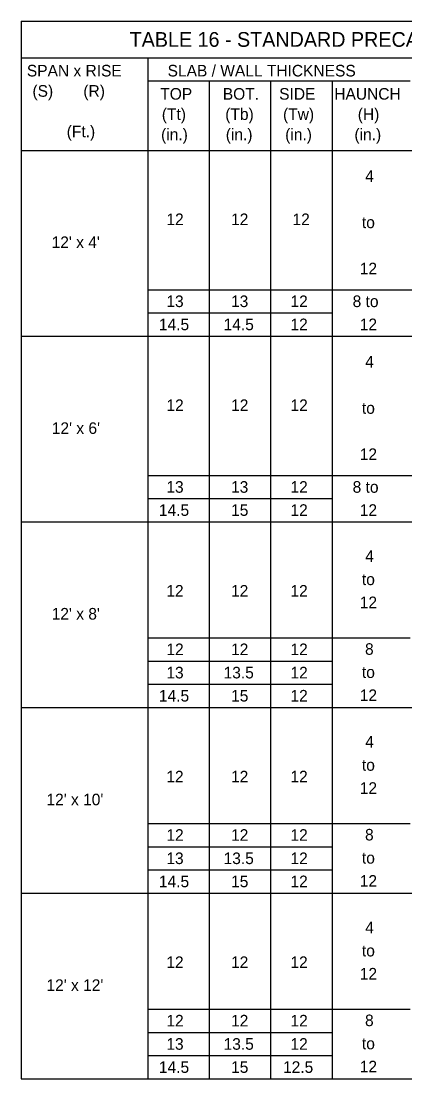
# Model space of a CAD drawing. Extents: x 10340.6 to 10376, y 76398.7 to 76415.8.
# Drawn here: x 10341.03 to 10344.36, y 76405.12 to 76414.31 of the extents above; entities that cross this region are included whole.
import ezdxf

# ---------------------------------------------------------------- set-up
doc = ezdxf.new("R2010")
doc.units = 0
doc.layers.add('AdhocPoint_dp', color=7, linetype='Continuous')
doc.layers.add('PlotBorder_dp', color=7, linetype='Continuous')

msp = doc.modelspace()

# ---------------------------------------------------------------- linework, layer by layer
at = {"layer": 'PlotBorder_dp'}
for p, q in [((10341.0317, 76414.3084), (10341.0317, 76405.1209)), ((10341.0317, 76414.3084), (10350.5475, 76414.3084)), ((10341.0317, 76413.9906), (10350.5475, 76413.9906)), ((10342.1299, 76413.9906), (10342.1299, 76405.1209)), ((10342.1299, 76413.789), (10344.409, 76413.789)), ((10342.6637, 76413.789), (10342.6637, 76405.1209)), ((10343.1974, 76413.789), (10343.1974, 76405.1209)), ((10343.7312, 76413.789), (10343.7312, 76405.1209)), ((10341.0317, 76413.185), (10350.5475, 76413.185)), ((10342.1299, 76411.9753), (10349.3093, 76411.9753)), ((10342.1299, 76411.7737), (10343.7312, 76411.7737)), ((10341.0317, 76411.5721), (10349.3093, 76411.5721)), ((10342.1299, 76410.3625), (10349.3093, 76410.3625)), ((10342.1299, 76410.1609), (10343.7312, 76410.1609)), ((10342.1299, 76410.1606), (10343.7312, 76410.1606)), ((10341.0317, 76409.9593), (10349.3093, 76409.9593)), ((10342.1299, 76408.9513), (10344.409, 76408.9513)), ((10342.1299, 76408.7497), (10343.7312, 76408.7497)), ((10342.1299, 76408.5481), (10343.7312, 76408.5481)), ((10341.0317, 76408.3465), (10349.3093, 76408.3465)), ((10342.1299, 76407.3385), (10344.409, 76407.3385)), ((10342.1299, 76407.1369), (10343.7312, 76407.1369)), ((10342.1299, 76406.9353), (10343.7312, 76406.9353)), ((10341.0317, 76406.7337), (10349.3093, 76406.7337)), ((10342.1299, 76405.7257), (10344.409, 76405.7257)), ((10342.1299, 76405.5241), (10343.7312, 76405.5241)), ((10342.1299, 76405.3225), (10343.7312, 76405.3225)), ((10341.0317, 76405.1209), (10350.5475, 76405.1209))]:
    msp.add_line(p, q, dxfattribs=at)

# ---------------------------------------------------------------- texts
at = {"layer": 'AdhocPoint_dp'}
for s, height, p in [('TABLE 16 - STANDARD PRECAST BOX CULVERT DESIGNS (3" COVER) - 12\' SPANS', 0.128, (10341.9731, 76414.0855)), ('SLAB / WALL THICKNESS', 0.1008, (10342.303, 76413.828)), ('12', 0.1008, (10342.2922, 76412.5368)), ('12', 0.1008, (10342.8536, 76412.5368)), ('12', 0.1008, (10343.3874, 76412.5368)), ("12' x 4'", 0.1008, (10341.2963, 76412.3377))]:
    msp.add_text(s, height=height, dxfattribs=at).set_placement(p)
at = {"layer": 'PlotBorder_dp'}
for s, p in [('SPAN x RISE', (10341.0811, 76413.828)), ('(S)       (R)', (10341.1298, 76413.652)), ('TOP', (10342.2391, 76413.6264)), ('BOT.', (10342.782, 76413.6264)), ('SIDE', (10343.2715, 76413.6264)), ('HAUNCH', (10343.7498, 76413.6264)), ('(Tt)', (10342.2526, 76413.4504)), ('(Tb)', (10342.8034, 76413.4504)), ('(Tw)', (10343.3051, 76413.4504)), ('(H)', (10343.9536, 76413.4504)), ('(Ft.)', (10341.427, 76413.3)), ('(in.)', (10342.2463, 76413.2744)), ('(in.)', (10342.8078, 76413.2744)), ('(in.)', (10343.3236, 76413.2744)), ('(in.)', (10343.9247, 76413.2744)), ('4', (10344.0183, 76412.9123)), ('to', (10343.9898, 76412.5107)), ('12', (10343.971, 76412.1091)), ('13', (10342.2921, 76411.8247)), ('13', (10342.8536, 76411.8247)), ('12', (10343.3695, 76411.8247)), ('8 to', (10343.9092, 76411.8247)), ('14.5', (10342.2275, 76411.6239)), ('14.5', (10342.789, 76411.6239)), ('12', (10343.3695, 76411.6239)), ('12', (10343.971, 76411.6239)), ('4', (10344.0183, 76411.2995)), ('12', (10342.2927, 76410.9219)), ('12', (10342.8541, 76410.9219)), ('12', (10343.3699, 76410.9219)), ('to', (10343.9898, 76410.8979)), ("12' x 6'", (10341.2974, 76410.7228)), ('12', (10343.971, 76410.4963)), ('13', (10342.2921, 76410.2119)), ('13', (10342.8536, 76410.2119)), ('12', (10343.3695, 76410.2119)), ('8 to', (10343.9092, 76410.2119)), ('14.5', (10342.2275, 76410.0111)), ('15', (10342.8541, 76410.0111)), ('12', (10343.3695, 76410.0111)), ('12', (10343.971, 76410.0111)), ('4', (10344.0183, 76409.6108)), ('to', (10343.9898, 76409.41)), ('12', (10342.2918, 76409.3094)), ('12', (10342.8533, 76409.3094)), ('12', (10343.3691, 76409.3094)), ('12', (10343.971, 76409.2092)), ("12' x 8'", (10341.2966, 76409.1103)), ('12', (10342.2922, 76408.8015)), ('12', (10342.8536, 76408.8015)), ('12', (10343.3694, 76408.8015)), ('8', (10344.0166, 76408.8041)), ('13', (10342.2921, 76408.5991)), ('13.5', (10342.789, 76408.5991)), ('12', (10343.3695, 76408.5991)), ('to', (10343.9898, 76408.6033)), ('12', (10343.3695, 76408.3983)), ('12', (10343.971, 76408.4025)), ('14.5', (10342.2275, 76408.3983)), ('15', (10342.8541, 76408.3983)), ('4', (10344.0183, 76407.998)), ('to', (10343.9898, 76407.7972)), ('12', (10342.2918, 76407.6961)), ('12', (10342.8533, 76407.6961)), ('12', (10343.3691, 76407.6961)), ('12', (10343.971, 76407.5964)), ("12' x 10'", (10341.2513, 76407.497)), ('12', (10342.2922, 76407.1887)), ('12', (10342.8536, 76407.1887)), ('12', (10343.3694, 76407.1887)), ('8', (10344.0166, 76407.1913)), ('13', (10342.2921, 76406.9863)), ('13.5', (10342.789, 76406.9863)), ('12', (10343.3695, 76406.9863)), ('to', (10343.9898, 76406.9905)), ('14.5', (10342.2275, 76406.7855)), ('15', (10342.8541, 76406.7855)), ('12', (10343.3695, 76406.7855)), ('12', (10343.971, 76406.7897)), ('4', (10344.0183, 76406.3852)), ('to', (10343.9898, 76406.1844)), ('12', (10342.2918, 76406.0836)), ('12', (10342.8533, 76406.0836)), ('12', (10343.3691, 76406.0836)), ('12', (10343.971, 76405.9836)), ("12' x 12'", (10341.2513, 76405.8845)), ('12', (10342.2922, 76405.5759)), ('12', (10342.8536, 76405.5759)), ('12', (10343.3694, 76405.5759)), ('8', (10344.0166, 76405.5785)), ('13', (10342.2921, 76405.3735)), ('13.5', (10342.789, 76405.3735)), ('12', (10343.3695, 76405.3735)), ('to', (10343.9898, 76405.3777)), ('14.5', (10342.2275, 76405.1727)), ('15', (10342.8541, 76405.1727)), ('12.5', (10343.3048, 76405.1727)), ('12', (10343.971, 76405.1769))]:
    msp.add_text(s, height=0.1008, dxfattribs=at).set_placement(p)

doc.saveas('drawing.dxf')
